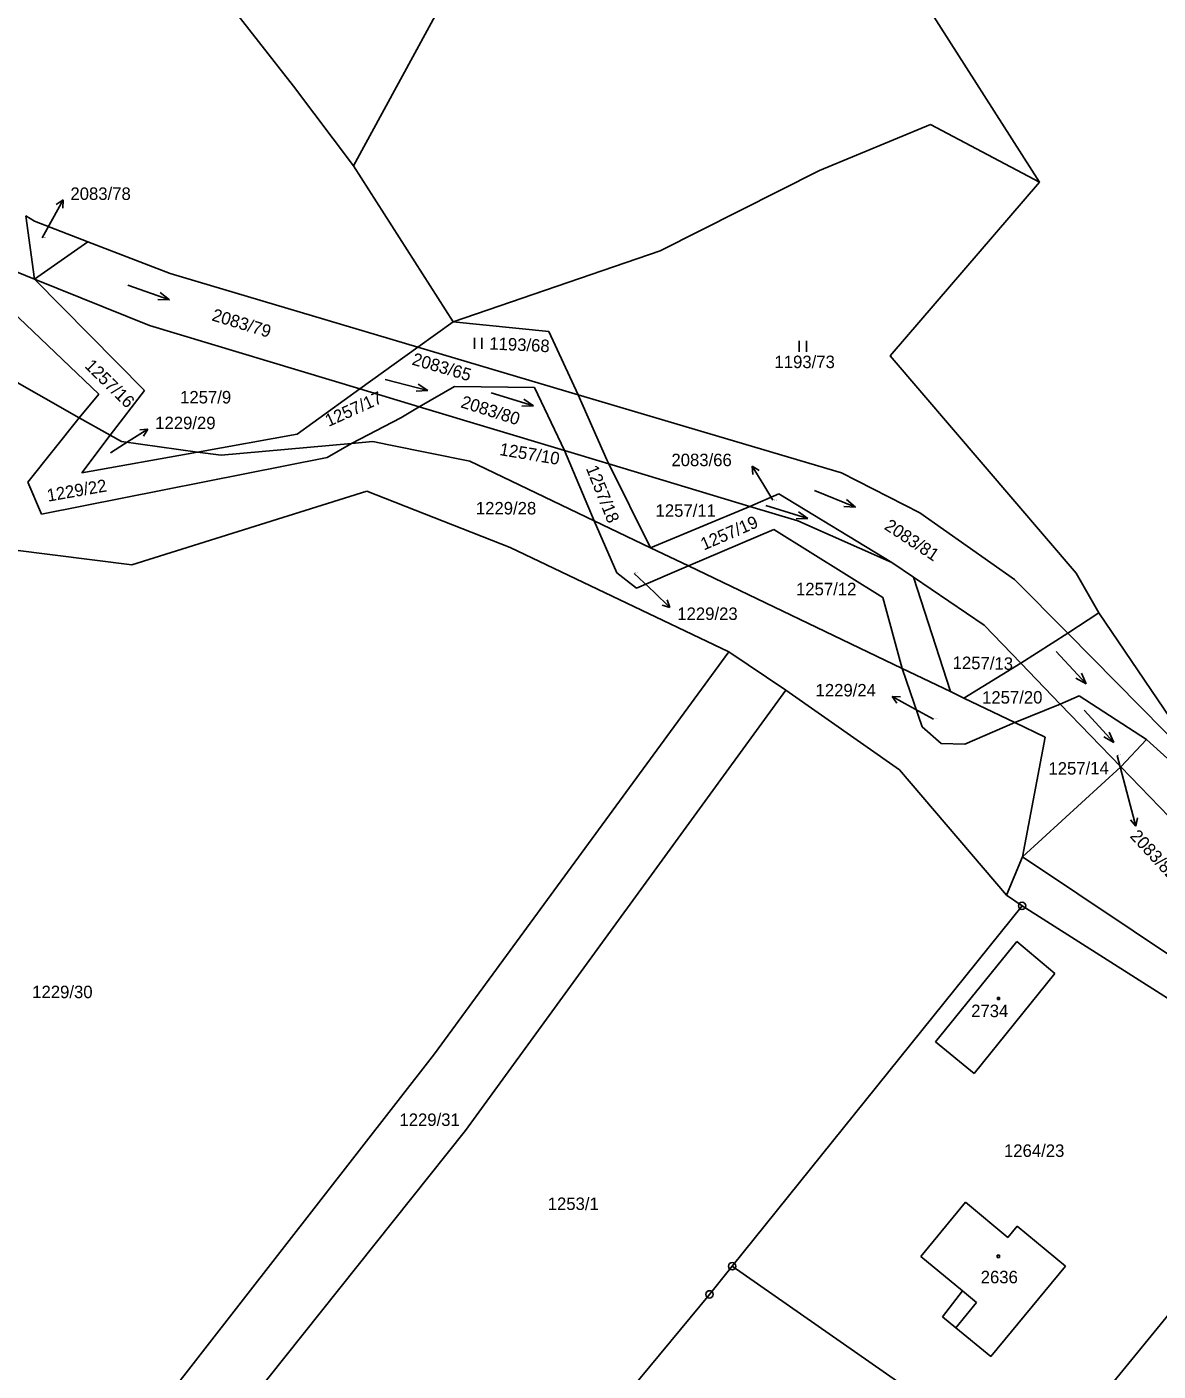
# Model space of a CAD drawing. Extents: x -795483 to -789093, y -1112258 to -1108741.
# Drawn here: x -792910.5 to -792756.5, y -1109807.4 to -1109624.3 of the extents above; entities that cross this region are included whole.
import ezdxf

# ---------------------------------------------------------------- set-up
doc = ezdxf.new("R2010")
doc.units = 0
for name, color, linetype in [('Komunikace', 7, 'Continuous'), ('Vrstva 1', 7, 'Continuous'), ('Vrstva 14', 7, 'Continuous'), ('Vrstva 15', 7, 'Continuous'), ('Vrstva 16', 7, 'Continuous'), ('Vrstva 2', 7, 'Continuous'), ('Vrstva 23', 7, 'Continuous'), ('Vrstva 25', 7, 'Continuous'), ('Vrstva 28', 7, 'Continuous')]:
    doc.layers.add(name, color=color, linetype=linetype)

msp = doc.modelspace()

# ---------------------------------------------------------------- linework, layer by layer
at = {"layer": 'Komunikace'}
for p, q in [((-792908.4, -1109653.07), (-792906.99, -1109650.53)), ((-792899.09, -1109682.35), (-792896.53, -1109680.72)), ((-792808.91, -1109688.8), (-792810.17, -1109686.72)), ((-792827.79, -1109698.76), (-792825.1, -1109701.32)), ((-792787.04, -1109718.58), (-792790.04, -1109716.94)), ((-792762.04, -1109723.53), (-792760.27, -1109730.24))]:
    msp.add_line(p, q, dxfattribs=at)
at = {"layer": 'Vrstva 1'}
for p, q in [((-792821.77, -1109568.51), (-792772.61, -1109645.46)), ((-792846.09, -1109606.68), (-792866, -1109643.24)), ((-792874.16, -1109632.39), (-792888.4, -1109614.2)), ((-792874.16, -1109632.39), (-792866, -1109643.24)), ((-792802.57, -1109643.91), (-792787.46, -1109637.61)), ((-792787.46, -1109637.61), (-792772.61, -1109645.46)), ((-792852.45, -1109664.49), (-792866, -1109643.24)), ((-792824.27, -1109654.85), (-792802.57, -1109643.91)), ((-792772.61, -1109645.46), (-792792.96, -1109669.12)), ((-792909.44, -1109658.67), (-792910.61, -1109650.08)), ((-792910.61, -1109650.08), (-792909.43, -1109650.81)), ((-792909.43, -1109650.81), (-792902.17, -1109653.61)), ((-792902.17, -1109653.61), (-792909.44, -1109658.67)), ((-792902.17, -1109653.61), (-792890.94, -1109657.93)), ((-792852.45, -1109664.49), (-792824.27, -1109654.85)), ((-792914.97, -1109656.44), (-792909.44, -1109658.67)), ((-792909.44, -1109658.67), (-792893.79, -1109664.99)), ((-792894.47, -1109673.84), (-792909.44, -1109658.67)), ((-792890.94, -1109657.93), (-792857.24, -1109667.94)), ((-792913.56, -1109662.06), (-792900.69, -1109674.36)), ((-792893.79, -1109664.99), (-792865.15, -1109673.63)), ((-792852.45, -1109664.49), (-792857.24, -1109667.94)), ((-792839.4, -1109665.82), (-792852.45, -1109664.49)), ((-792835.44, -1109674.42), (-792839.4, -1109665.82)), ((-792857.24, -1109667.94), (-792865.15, -1109673.63)), ((-792857.24, -1109667.94), (-792835.44, -1109674.42)), ((-792792.96, -1109669.12), (-792767.65, -1109698.72)), ((-792914.39, -1109671.31), (-792903.33, -1109677.56)), ((-792899.11, -1109679.95), (-792894.47, -1109673.84)), ((-792865.15, -1109673.63), (-792873.69, -1109679.78)), ((-792865.15, -1109673.63), (-792857.09, -1109676.06)), ((-792857.09, -1109676.06), (-792852.24, -1109673.28)), ((-792852.24, -1109673.28), (-792841.36, -1109673.42)), ((-792841.36, -1109673.42), (-792837.29, -1109682.03)), ((-792900.69, -1109674.36), (-792903.33, -1109677.56)), ((-792831.53, -1109683.27), (-792835.44, -1109674.42)), ((-792835.44, -1109674.42), (-792799.59, -1109685.07)), ((-792903.33, -1109677.56), (-792910.32, -1109686.31)), ((-792903.33, -1109677.56), (-792899.11, -1109679.95)), ((-792866.27, -1109681.05), (-792859.57, -1109677.55)), ((-792859.57, -1109677.55), (-792857.09, -1109676.06)), ((-792857.09, -1109676.06), (-792837.29, -1109682.03)), ((-792902.99, -1109685.05), (-792899.11, -1109679.95)), ((-792899.11, -1109679.95), (-792897.6, -1109680.8)), ((-792897.6, -1109680.8), (-792887.25, -1109682.22)), ((-792873.69, -1109679.78), (-792887.25, -1109682.22)), ((-792884.03, -1109682.66), (-792866.27, -1109681.05)), ((-792869.57, -1109682.98), (-792866.27, -1109681.05)), ((-792866.27, -1109681.05), (-792863.36, -1109680.79)), ((-792863.36, -1109680.79), (-792861.2, -1109681.23)), ((-792861.2, -1109681.23), (-792850.17, -1109683.45)), ((-792908.48, -1109690.67), (-792869.57, -1109682.98)), ((-792887.25, -1109682.22), (-792902.99, -1109685.05)), ((-792887.25, -1109682.22), (-792884.03, -1109682.66)), ((-792837.29, -1109682.03), (-792833.25, -1109691.57)), ((-792837.29, -1109682.03), (-792831.24, -1109683.85)), ((-792831.24, -1109683.85), (-792831.53, -1109683.27)), ((-792850.17, -1109683.45), (-792833.25, -1109691.57)), ((-792831.24, -1109683.85), (-792812.05, -1109689.64)), ((-792825.57, -1109695.26), (-792831.24, -1109683.85)), ((-792799.59, -1109685.07), (-792788.92, -1109690.48)), ((-792910.32, -1109686.31), (-792908.48, -1109690.67)), ((-792864.21, -1109687.55), (-792896.16, -1109697.59)), ((-792844.69, -1109695.21), (-792864.21, -1109687.55)), ((-792808.11, -1109687.93), (-792812.05, -1109689.64)), ((-792792.71, -1109697.28), (-792808.11, -1109687.93)), ((-792812.05, -1109689.64), (-792825.57, -1109695.26)), ((-792812.05, -1109689.64), (-792805.53, -1109691.61)), ((-792788.92, -1109690.48), (-792776.04, -1109699.56)), ((-792833.25, -1109691.57), (-792825.57, -1109695.26)), ((-792833.25, -1109691.57), (-792830.16, -1109698.69)), ((-792805.53, -1109691.61), (-792792.71, -1109697.28)), ((-792820.4, -1109697.74), (-792808.81, -1109692.77)), ((-792808.81, -1109692.77), (-792793.97, -1109702.04)), ((-792896.16, -1109697.59), (-792912.37, -1109695.54)), ((-792814.9, -1109709.42), (-792844.69, -1109695.21)), ((-792825.57, -1109695.26), (-792820.4, -1109697.74)), ((-792827.49, -1109700.77), (-792820.4, -1109697.74)), ((-792820.4, -1109697.74), (-792791.32, -1109711.7)), ((-792792.71, -1109697.28), (-792789.79, -1109699.26)), ((-792830.16, -1109698.69), (-792827.49, -1109700.77)), ((-792789.79, -1109699.26), (-792780.16, -1109705.79)), ((-792784.76, -1109714.85), (-792789.79, -1109699.26)), ((-792776.04, -1109699.56), (-792768.79, -1109706.9)), ((-792767.65, -1109698.72), (-792764.53, -1109704.11)), ((-792793.97, -1109702.04), (-792791.32, -1109711.7)), ((-792764.53, -1109704.11), (-792768.79, -1109706.9)), ((-792754.79, -1109718.49), (-792764.53, -1109704.11)), ((-792780.16, -1109705.79), (-792775.15, -1109710.99)), ((-792768.79, -1109706.9), (-792775.15, -1109710.99)), ((-792768.79, -1109706.9), (-792729.31, -1109746.88)), ((-792814.9, -1109709.42), (-792855, -1109764.15)), ((-792807.16, -1109714.63), (-792814.9, -1109709.42)), ((-792791.32, -1109711.7), (-792784.76, -1109714.85)), ((-792791.32, -1109711.7), (-792788.61, -1109719.65)), ((-792775.15, -1109710.99), (-792782.92, -1109715.74)), ((-792775.15, -1109710.99), (-792769.8, -1109716.53)), ((-792807.16, -1109714.63), (-792850.74, -1109774.59)), ((-792791.69, -1109725.51), (-792807.16, -1109714.63)), ((-792784.76, -1109714.85), (-792782.92, -1109715.74)), ((-792782.92, -1109715.74), (-792775.99, -1109719.07)), ((-792769.8, -1109716.53), (-792767.24, -1109715.4)), ((-792767.24, -1109715.4), (-792758.07, -1109721.37)), ((-792775.99, -1109719.07), (-792769.8, -1109716.53)), ((-792769.8, -1109716.53), (-792761.55, -1109725.09)), ((-792788.61, -1109719.65), (-792786.03, -1109721.89)), ((-792782.77, -1109721.99), (-792775.99, -1109719.07)), ((-792775.99, -1109719.07), (-792771.85, -1109721.06)), ((-792771.85, -1109721.06), (-792774.96, -1109737.34)), ((-792761.55, -1109725.09), (-792758.07, -1109721.37)), ((-792758.07, -1109721.37), (-792738.04, -1109739.55)), ((-792786.03, -1109721.89), (-792782.77, -1109721.99)), ((-792774.96, -1109737.34), (-792761.55, -1109725.09)), ((-792761.55, -1109725.09), (-792732.26, -1109755.48)), ((-792777.11, -1109742.55), (-792791.69, -1109725.51)), ((-792774.96, -1109737.34), (-792777.11, -1109742.55)), ((-792725.36, -1109770.56), (-792774.96, -1109737.34)), ((-792777.11, -1109742.55), (-792775, -1109744.01)), ((-792775, -1109744.01), (-792814.46, -1109793.08)), ((-792752.02, -1109758.6), (-792775, -1109744.01)), ((-792786.8, -1109762.54), (-792775.73, -1109748.85)), ((-792775.73, -1109748.85), (-792770.52, -1109753.23)), ((-792770.52, -1109753.23), (-792781.5, -1109766.85)), ((-792781.5, -1109766.85), (-792786.8, -1109762.54)), ((-792855, -1109764.15), (-792914.71, -1109840.87)), ((-792850.74, -1109774.59), (-792907.54, -1109845.75)), ((-792766.85, -1109814.09), (-792735.16, -1109775.24)), ((-792788.76, -1109791.74), (-792782.71, -1109784.37)), ((-792782.71, -1109784.37), (-792776.94, -1109789.16)), ((-792776.94, -1109789.16), (-792775.65, -1109787.63)), ((-792775.65, -1109787.63), (-792769.09, -1109793.05)), ((-792814.46, -1109793.08), (-792817.54, -1109796.91)), ((-792814.46, -1109793.08), (-792772.84, -1109822.08)), ((-792783.1, -1109796.43), (-792788.76, -1109791.74)), ((-792769.09, -1109793.05), (-792779.27, -1109805.37)), ((-792785.85, -1109799.96), (-792783.1, -1109796.43)), ((-792817.54, -1109796.91), (-792841.83, -1109826.25)), ((-792784.03, -1109801.45), (-792785.85, -1109799.96)), ((-792779.27, -1109805.37), (-792784.03, -1109801.45))]:
    msp.add_line(p, q, dxfattribs=at)
at = {"layer": 'Vrstva 16'}
for p, q in [((-792906.99, -1109650.53), (-792905.54, -1109647.9)), ((-792905.54, -1109647.9), (-792906.46, -1109648.54)), ((-792905.54, -1109647.9), (-792905.58, -1109649.02)), ((-792896.53, -1109680.72), (-792894, -1109679.11)), ((-792894, -1109679.11), (-792895.11, -1109679.22)), ((-792894, -1109679.11), (-792894.57, -1109680.07)), ((-792810.17, -1109686.72), (-792811.72, -1109684.15)), ((-792811.72, -1109684.15), (-792811.63, -1109685.27)), ((-792811.72, -1109684.15), (-792810.78, -1109684.75)), ((-792825.1, -1109701.32), (-792822.93, -1109703.39)), ((-792822.93, -1109703.39), (-792824, -1109703.06)), ((-792822.93, -1109703.39), (-792823.31, -1109702.34)), ((-792790.04, -1109716.94), (-792792.67, -1109715.5)), ((-792792.67, -1109715.5), (-792792.03, -1109716.42)), ((-792792.67, -1109715.5), (-792791.55, -1109715.54)), ((-792760.27, -1109730.24), (-792759.51, -1109733.14)), ((-792759.51, -1109733.14), (-792760.24, -1109732.3)), ((-792759.51, -1109733.14), (-792759.28, -1109732.05))]:
    msp.add_line(p, q, dxfattribs=at)
at = {"layer": 'Vrstva 2'}
for p, q in [((-792781.19, -1109798.02), (-792783.1, -1109796.43)), ((-792784.03, -1109801.45), (-792781.19, -1109798.02))]:
    msp.add_line(p, q, dxfattribs=at)
at = {"layer": 'Vrstva 23'}
for p, q in [((-792896.72, -1109659.49), (-792891.06, -1109661.49)), ((-792891.06, -1109661.49), (-792892.31, -1109660.52)), ((-792891.06, -1109661.49), (-792892.64, -1109661.46)), ((-792849.55, -1109668.19), (-792849.55, -1109666.69)), ((-792848.55, -1109666.69), (-792848.55, -1109668.19)), ((-792805.35, -1109668.6), (-792805.35, -1109667.1)), ((-792804.35, -1109667.1), (-792804.35, -1109668.6)), ((-792861.69, -1109672.33), (-792855.89, -1109673.83)), ((-792855.89, -1109673.83), (-792857.46, -1109673.94)), ((-792855.89, -1109673.83), (-792857.21, -1109672.97)), ((-792847.25, -1109674.18), (-792841.51, -1109675.94)), ((-792841.51, -1109675.94), (-792843.09, -1109675.98)), ((-792841.51, -1109675.94), (-792842.8, -1109675.02)), ((-792803.25, -1109687.46), (-792797.69, -1109689.72)), ((-792797.69, -1109689.72), (-792798.89, -1109688.69)), ((-792809.89, -1109689.51), (-792804.17, -1109691.29)), ((-792804.17, -1109691.29), (-792805.45, -1109690.37)), ((-792797.69, -1109689.72), (-792799.27, -1109689.62)), ((-792804.17, -1109691.29), (-792805.75, -1109691.32)), ((-792770.35, -1109709.38), (-792766.27, -1109713.78)), ((-792766.27, -1109713.78), (-792766.92, -1109712.34)), ((-792766.27, -1109713.78), (-792767.66, -1109713.02)), ((-792766.56, -1109717.37), (-792762.5, -1109721.79)), ((-792762.5, -1109721.79), (-792763.89, -1109721.02)), ((-792762.5, -1109721.79), (-792763.15, -1109720.35))]:
    msp.add_line(p, q, dxfattribs=at)
at = {"layer": 'Vrstva 25'}
for p, q in [((-792778.36, -1109756.47), (-792778.06, -1109756.47)), ((-792778.36, -1109756.77), (-792778.36, -1109756.47)), ((-792778.06, -1109756.47), (-792778.06, -1109756.77)), ((-792778.06, -1109756.77), (-792778.36, -1109756.77)), ((-792778.37, -1109791.59), (-792778.07, -1109791.59)), ((-792778.37, -1109791.89), (-792778.37, -1109791.59)), ((-792778.07, -1109791.89), (-792778.37, -1109791.89)), ((-792778.07, -1109791.59), (-792778.07, -1109791.89))]:
    msp.add_line(p, q, dxfattribs=at)
at = {"layer": 'Vrstva 28'}
for centre, radius in [((-792775, -1109744.01), 0.5), ((-792775, -1109744.01), 0.01), ((-792814.46, -1109793.08), 0.5), ((-792814.46, -1109793.08), 0.01), ((-792817.54, -1109796.91), 0.5), ((-792817.54, -1109796.91), 0.01)]:
    msp.add_circle(centre, radius, dxfattribs=at)

# ---------------------------------------------------------------- texts
at = {"layer": 'Vrstva 14'}
for s, height, p in [('2083/78', 0.1, (-792908.4, -1109653.07)), ('1193/73', 1.7, (-792808.7, -1109670.8)), ('1257/9', 1.7, (-792889.61, -1109675.61)), ('1229/29', 0.1, (-792899.09, -1109682.35)), ('2083/66', 0.1, (-792808.91, -1109688.8)), ('1229/28', 1.7, (-792849.35, -1109690.72)), ('1257/11', 1.7, (-792824.89, -1109691.04)), ('1229/23', 0.1, (-792827.79, -1109698.76)), ('1257/12', 1.7, (-792805.77, -1109701.73)), ('1229/24', 0.1, (-792787.04, -1109718.58)), ('2083/82', 0.1, (-792762.04, -1109723.53)), ('1229/30', 1.7, (-792909.74, -1109756.58)), ('1229/31', 1.7, (-792859.75, -1109773.98)), ('1264/23', 1.7, (-792777.46, -1109778.19)), ('1253/1', 1.7, (-792839.57, -1109785.42))]:
    msp.add_text(s, height=height, dxfattribs=at).set_placement(p)
for s, rotation, p in [('2083/79', 342.9732, (-792885.4, -1109664.28)), ('1193/68', 357.3466, (-792847.55, -1109668.26)), ('1257/16', 315.6682, (-792902.71, -1109670.62)), ('2083/65', 343.7563, (-792858.16, -1109670.3)), ('1257/17', 24.2607, (-792869.4, -1109678.82)), ('2083/80', 342.4026, (-792851.52, -1109676.11)), ('1257/10', 350.4862, (-792846.21, -1109682.63)), ('1257/18', 291.9252, (-792834.4, -1109684.43)), ('1229/22', 9.9229, (-792907.58, -1109688.99)), ('1257/19', 23.3302, (-792818.31, -1109695.64)), ('2083/81', 326.5542, (-792793.88, -1109692.64)), ('1257/13', 358.9601, (-792784.46, -1109711.74)), ('1257/20', 0.2139, (-792780.44, -1109716.49)), ('1257/14', 0.5668, (-792771.4, -1109726.17))]:
    msp.add_text(s, height=1.7, rotation=rotation, dxfattribs=at).set_placement(p)
at = {"layer": 'Vrstva 15'}
for s, p in [('2734', (-792781.93, -1109759.16)), ('2636', (-792780.63, -1109795.4))]:
    msp.add_text(s, height=1.7, dxfattribs=at).set_placement(p)
at = {"layer": 'Vrstva 16'}
for s, p in [('2083/78', (-792904.54, -1109647.9)), ('1229/29', (-792893, -1109679.11)), ('2083/66', (-792822.73, -1109684.15)), ('1229/23', (-792821.93, -1109705.09)), ('1229/24', (-792803.11, -1109715.5))]:
    msp.add_text(s, height=1.7, dxfattribs=at).set_placement(p)
msp.add_text('2083/82', height=1.7, rotation=312.7591, dxfattribs=at).set_placement((-792760.41, -1109734.59))

doc.saveas('drawing.dxf')
